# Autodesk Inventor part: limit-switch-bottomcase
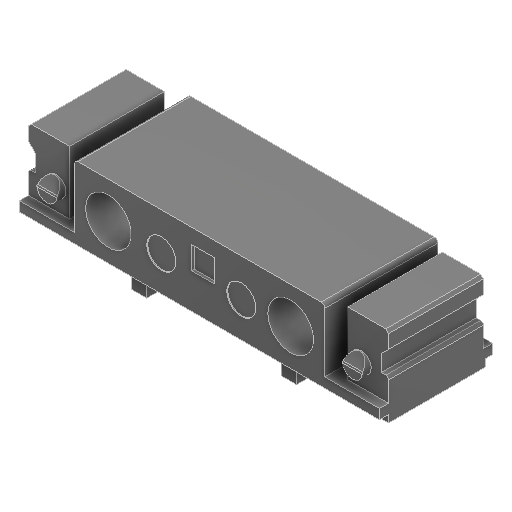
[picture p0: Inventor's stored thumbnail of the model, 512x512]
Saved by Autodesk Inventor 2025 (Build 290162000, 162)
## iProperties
Created: 2025-10
Part Number: limit-switch-bottomcase
Material: Generico
Document SubType Name: Modeling
Designer: Ryzen5700u
Density: 1 g/cm^3
Appearance: Default
Author: Ryzen5700u
Revision Number: ANY
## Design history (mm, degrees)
feature "Cut-Extrude14"
node "Solido1"
